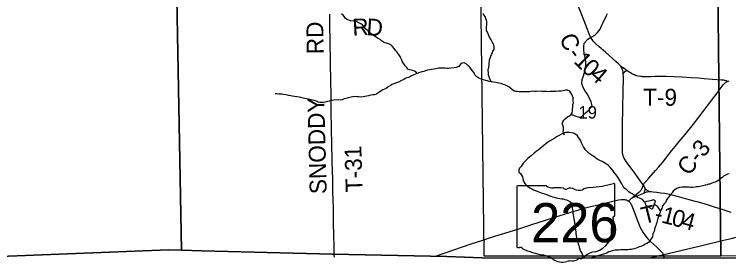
# Model space of a CAD drawing. Extents: x 1985906 to 2360102, y 891258 to 1222054.
# Drawn here: x 2069216 to 2081902, y 971985 to 976398 of the extents above; entities that cross this region are included whole.
import ezdxf

# ---------------------------------------------------------------- set-up
doc = ezdxf.new("R2010")
doc.units = 0
for name, color, linetype in [('GM_X_Adjacent_County', 7, 'Continuous'), ('GM_X_County', 7, 'Continuous'), ('GM_X_County_Road', 7, 'Continuous'), ('GM_X_County_Road_Text', 7, 'Continuous'), ('GM_X_Minor_Lake', 7, 'Continuous'), ('GM_X_Minor_River', 7, 'Continuous'), ('GM_X_Rail_Line', 7, 'Continuous'), ('GM_X_Section', 7, 'Continuous'), ('GM_X_Section_Text', 7, 'Continuous'), ('GM_X_State_Location', 7, 'Continuous'), ('GM_X_State_Route', 7, 'Continuous'), ('GM_X_State_Shield', 7, 'Continuous'), ('GM_X_Township', 7, 'Continuous'), ('GM_X_Township_Road', 7, 'Continuous'), ('GM_X_Township_Road_Text', 7, 'Continuous')]:
    doc.layers.add(name, color=color, linetype=linetype)

msp = doc.modelspace()

# ---------------------------------------------------------------- linework, layer by layer
at = {"layer": 'GM_X_Adjacent_County'}
for points in [[(2071861, 1011952), (2071887, 1008769), (2071889, 1006520), (2071959, 1001676), (2072021, 996047), (2072065, 993379), (2071978, 993380), (2071988, 991894), (2071996, 990692), (2072013, 988008), (2072047, 982707), (2072077, 978079), (2072089, 977430), (2072091, 977317), (2072186, 972205), (2071957, 972211), (2068961, 972095)], [(2068961, 972095), (2071957, 972211), (2072186, 972205), (2072548, 972195), (2074867, 972135), (2076899, 972093), (2077526, 972072), (2080743, 972068), (2082040, 972070), (2083320, 972078), (2085836, 972133), (2087953, 972142), (2092530, 972203), (2095843, 972202)]]:
    msp.add_lwpolyline(points, dxfattribs=at)
at = {"layer": 'GM_X_County'}
msp.add_lwpolyline([(2095843, 972202), (2092530, 972203), (2087953, 972142), (2085836, 972133), (2083320, 972078), (2082040, 972070), (2080743, 972068), (2077526, 972072), (2076899, 972093), (2074867, 972135), (2072548, 972195), (2072186, 972205), (2072091, 977317), (2072089, 977430), (2072077, 978079), (2072047, 982707), (2072013, 988008)], dxfattribs=at)
at = {"layer": 'GM_X_County_Road'}
for points in [[(2079976, 975485), (2079945, 975515), (2079898, 975559), (2079715, 975722), (2079604, 975819), (2079543, 975874), (2079520, 975898), (2079498, 975922), (2079477, 975948), (2079459, 975976), (2079444, 976005), (2079424, 976051), (2079382, 976158), (2079336, 976281), (2079280, 976418), (2079139, 976768), (2079078, 976921)], [(2080031, 975335), (2080031, 975345), (2080026, 975375), (2080020, 975399), (2080012, 975421), (2079996, 975451), (2079988, 975464), (2079976, 975485)], [(2080386, 973366), (2080297, 973492), (2080239, 973572), (2080187, 973643), (2080111, 973742), (2080082, 973783), (2080064, 973810), (2080048, 973839), (2080034, 973867), (2080027, 973887), (2080022, 973910), (2080018, 973934), (2080015, 973968), (2080015, 974066), (2080016, 974182), (2080017, 974265), (2080016, 974322), (2080019, 974507), (2080020, 974652), (2080024, 974803), (2080029, 974967), (2080031, 975065), (2080035, 975230), (2080034, 975295), (2080031, 975335)], [(2080386, 973366), (2080395, 973383), (2080403, 973395), (2080413, 973408), (2080428, 973426), (2080482, 973487), (2080602, 973622), (2080655, 973684), (2080730, 973772), (2080792, 973848), (2080829, 973896), (2080895, 973977), (2080954, 974048), (2081024, 974136), (2081132, 974265), (2081276, 974447), (2081388, 974594), (2081467, 974696), (2081540, 974790), (2081583, 974847), (2081634, 974914), (2081677, 974971), (2081720, 975030), (2081753, 975073), (2081770, 975097), (2081787, 975120), (2081812, 975151), (2081829, 975169), (2081841, 975180), (2081853, 975188), (2081861, 975195), (2081872, 975201), (2081883, 975206)], [(2081883, 975206), (2081895, 975210), (2081909, 975214)], [(2080194, 973146), (2080213, 973162), (2080236, 973181), (2080269, 973207), (2080307, 973237), (2080323, 973249), (2080333, 973258), (2080342, 973267), (2080350, 973278), (2080359, 973290), (2080368, 973311), (2080375, 973331), (2080386, 973366)], [(2080125, 973079), (2080147, 973101), (2080177, 973131), (2080192, 973144), (2080194, 973146)]]:
    msp.add_lwpolyline(points, dxfattribs=at)
at = {"layer": 'GM_X_Minor_Lake'}
for points in [[(2080604, 973077), (2080566, 973099), (2080532, 973089), (2080486, 973077), (2080442, 973074), (2080414, 973058), (2080426, 973016), (2080531, 972942), (2080553, 972949)], [(2080553, 972949), (2080604, 973077)]]:
    msp.add_lwpolyline(points, dxfattribs=at)
at = {"layer": 'GM_X_Minor_River'}
for points in [[(2076368, 975344), (2076350, 975368), (2076322, 975389), (2076291, 975401), (2076263, 975407), (2076233, 975413), (2076207, 975423), (2076184, 975451), (2076158, 975481), (2076136, 975515), (2076110, 975553), (2076095, 975581), (2076079, 975620), (2076067, 975650), (2076045, 975686), (2076011, 975728), (2075988, 975756), (2075962, 975788), (2075934, 975824), (2075905, 975855), (2075879, 975869), (2075825, 975885), (2075797, 975893), (2075770, 975901), (2075738, 975925), (2075712, 975949), (2075680, 975969), (2075633, 975995), (2075607, 976015), (2075577, 976033), (2075550, 976054), (2075524, 976082), (2075496, 976106), (2075455, 976142), (2075429, 976174), (2075399, 976210), (2075371, 976226), (2075344, 976238), (2075300, 976264), (2075270, 976275), (2075238, 976277), (2075185, 976281), (2075155, 976293), (2075127, 976307), (2075100, 976325), (2075080, 976351), (2075054, 976383), (2075026, 976405)], [(2077702, 975195), (2077684, 975197), (2077660, 975251), (2077650, 975284), (2077638, 975318), (2077635, 975352), (2077631, 975404), (2077641, 975458), (2077647, 975490), (2077649, 975528), (2077653, 975563), (2077655, 975589), (2077665, 975619), (2077681, 975655), (2077693, 975681), (2077705, 975713), (2077715, 975741), (2077735, 975775), (2077739, 975815), (2077729, 975852), (2077719, 975878), (2077703, 975908), (2077682, 975946), (2077654, 975994), (2077644, 976020), (2077628, 976048), (2077618, 976077), (2077603, 976111), (2077599, 976147), (2077599, 976173), (2077605, 976213), (2077609, 976245), (2077605, 976271), (2077591, 976322), (2077581, 976348), (2077561, 976380), (2077542, 976414)], [(2079106, 974622), (2079168, 974593), (2079244, 974573), (2079296, 974582), (2079358, 974650), (2079426, 974700), (2079478, 974770), (2079459, 974845), (2079419, 974931), (2079389, 974985), (2079349, 975045), (2079316, 975097), (2079294, 975167), (2079302, 975237), (2079320, 975287), (2079339, 975363), (2079355, 975427), (2079365, 975479), (2079365, 975560), (2079356, 975632), (2079338, 975708), (2079328, 975766), (2079328, 975826), (2079337, 975882), (2079401, 975954), (2079469, 975995), (2079523, 976029), (2079575, 976075), (2079620, 976136), (2079652, 976202), (2079672, 976254), (2079724, 976362), (2079751, 976413)], [(2078971, 974286), (2078978, 974259), (2078964, 974301), (2078966, 974357), (2078968, 974391), (2078955, 974426), (2078947, 974454), (2078955, 974486), (2078973, 974516), (2079003, 974548), (2079042, 974574), (2079074, 974594), (2079102, 974616), (2079120, 974646), (2079126, 974682), (2079128, 974715), (2079132, 974755), (2079136, 974793), (2079144, 974827), (2079142, 974859), (2079142, 974887), (2079138, 974915), (2079130, 974941), (2079115, 974974), (2079101, 975002), (2079079, 975032), (2079039, 975052), (2079010, 975048), (2078960, 975038), (2078920, 975034), (2078885, 975032), (2078831, 975028), (2078783, 975024), (2078728, 975024), (2078700, 975022), (2078672, 975024), (2078626, 975026), (2078583, 975028), (2078555, 975030), (2078489, 975028), (2078454, 975028), (2078426, 975030), (2078362, 975022), (2078335, 975020), (2078295, 975020), (2078257, 975022), (2078217, 975020), (2078182, 975022), (2078154, 975024), (2078124, 975024), (2078096, 975034), (2078069, 975048), (2078037, 975072), (2077997, 975107), (2077964, 975127), (2077924, 975143), (2077888, 975155), (2077860, 975167), (2077821, 975173), (2077793, 975179), (2077765, 975185), (2077680, 975199), (2077650, 975203), (2077622, 975213), (2077591, 975223), (2077549, 975233), (2077523, 975243), (2077493, 975249), (2077466, 975264), (2077428, 975286), (2077396, 975322), (2077384, 975356), (2077351, 975394), (2077329, 975424), (2077299, 975464), (2077272, 975490), (2077240, 975515), (2077204, 975537), (2077172, 975531), (2077141, 975509), (2077109, 975472), (2077065, 975450), (2077025, 975444), (2076968, 975438), (2076926, 975436), (2076900, 975436), (2076868, 975439), (2076839, 975443), (2076795, 975443), (2076751, 975441), (2076702, 975431), (2076668, 975425), (2076630, 975419), (2076596, 975409), (2076553, 975403), (2076517, 975393), (2076487, 975384), (2076453, 975374), (2076418, 975362), (2076370, 975344), (2076338, 975334)], [(2076338, 975334), (2076310, 975324), (2076259, 975298), (2076223, 975276), (2076169, 975262), (2076131, 975240), (2076094, 975220), (2076038, 975192), (2076002, 975180), (2075955, 975164), (2075927, 975152), (2075897, 975134), (2075855, 975110), (2075819, 975080), (2075758, 975058), (2075726, 975034), (2075680, 975003), (2075646, 974979), (2075607, 974969), (2075581, 974965), (2075549, 974959), (2075505, 974947), (2075476, 974943), (2075442, 974935), (2075412, 974933), (2075376, 974927), (2075329, 974929), (2075303, 974933), (2075255, 974935), (2075227, 974931), (2075198, 974925), (2075172, 974921), (2075142, 974915), (2075106, 974903), (2075076, 974893), (2075039, 974877), (2075005, 974873), (2074967, 974881), (2074888, 974875), (2074846, 974865), (2074812, 974855), (2074777, 974847), (2074739, 974837), (2074699, 974833), (2074671, 974829), (2074644, 974829), (2074618, 974839), (2074582, 974855), (2074511, 974874), (2074443, 974888), (2074378, 974902), (2074348, 974908), (2074302, 974918), (2074273, 974924), (2074233, 974934), (2074153, 974942), (2074126, 974948), (2074088, 974956), (2074044, 974966), (2073995, 974972), (2073969, 974976), (2073937, 974980), (2073907, 974980), (2073876, 974982), (2073850, 974982)], [(2080414, 973058), (2080372, 973106), (2080348, 973121), (2080321, 973134), (2080290, 973146), (2080242, 973174), (2080191, 973206), (2080155, 973228), (2080129, 973244), (2080091, 973277), (2080056, 973305), (2080026, 973339), (2080004, 973385), (2079971, 973445), (2079935, 973505), (2079903, 973544), (2079870, 973590), (2079850, 973616), (2079828, 973644), (2079783, 973692), (2079759, 973720), (2079656, 973781), (2079614, 973803), (2079567, 973825), (2079535, 973845), (2079505, 973873), (2079462, 973899), (2079426, 973923), (2079394, 973953), (2079357, 973990), (2079323, 974042), (2079307, 974076), (2079291, 974114), (2079278, 974148), (2079258, 974180), (2079238, 974211), (2079220, 974237), (2079179, 974271), (2079147, 974287), (2079067, 974299), (2079034, 974297), (2079006, 974295), (2078958, 974283), (2078920, 974265), (2078881, 974241), (2078847, 974221), (2078817, 974199), (2078773, 974175), (2078720, 974141), (2078686, 974118), (2078660, 974100), (2078618, 974066), (2078586, 974038), (2078555, 974014), (2078521, 973984), (2078485, 973958), (2078449, 973928), (2078397, 973886), (2078370, 973866), (2078338, 973836), (2078304, 973806), (2078278, 973779), (2078252, 973751), (2078232, 973721), (2078214, 973695), (2078190, 973663), (2078173, 973635), (2078176, 973595), (2078204, 973567), (2078222, 973539), (2078238, 973508), (2078246, 973478), (2078254, 973450), (2078267, 973420), (2078283, 973392), (2078299, 973366), (2078337, 973336), (2078372, 973316), (2078404, 973300), (2078436, 973281), (2078481, 973259), (2078515, 973249), (2078541, 973239), (2078573, 973229), (2078632, 973207), (2078666, 973195), (2078745, 973169), (2078775, 973157), (2078803, 973147), (2078836, 973137)], [(2081913, 973561), (2081883, 973557), (2081843, 973541), (2081809, 973523), (2081783, 973492), (2081750, 973472), (2081726, 973452), (2081696, 973434), (2081660, 973414), (2081634, 973408), (2081593, 973392), (2081567, 973382), (2081543, 973378), (2081517, 973370), (2081487, 973360), (2081442, 973350), (2081416, 973344), (2081392, 973338), (2081360, 973334), (2081332, 973330), (2081307, 973326), (2081257, 973320), (2081231, 973320), (2081195, 973324), (2081164, 973328), (2081106, 973328), (2081068, 973324), (2081029, 973318), (2080981, 973306), (2080953, 973286), (2080919, 973256), (2080899, 973224), (2080869, 973196), (2080842, 973158), (2080810, 973122), (2080790, 973091), (2080786, 973063), (2080748, 973027), (2080734, 973001), (2080720, 972971), (2080716, 972947), (2080698, 972917), (2080688, 972889), (2080680, 972863), (2080664, 972822), (2080658, 972798), (2080644, 972774), (2080630, 972724), (2080626, 972698), (2080612, 972670), (2080606, 972644), (2080596, 972616), (2080586, 972586), (2080582, 972558), (2080568, 972523), (2080556, 972491), (2080548, 972443), (2080522, 972405), (2080506, 972377), (2080478, 972347), (2080447, 972325), (2080421, 972317), (2080393, 972299), (2080341, 972275), (2080315, 972265), (2080290, 972253), (2080262, 972244), (2080228, 972234), (2080194, 972226), (2080170, 972222), (2080141, 972218), (2080109, 972216)], [(2078836, 973137), (2078868, 973129), (2078906, 973125), (2078936, 973121), (2078963, 973117), (2078993, 973108), (2079019, 973104), (2079047, 973092), (2079084, 973074), (2079108, 973048), (2079116, 973018), (2079122, 972984), (2079124, 972956), (2079128, 972926), (2079132, 972900), (2079136, 972867), (2079143, 972835), (2079147, 972801), (2079155, 972763), (2079159, 972733), (2079163, 972705), (2079169, 972651), (2079173, 972606), (2079186, 972536), (2079190, 972502), (2079194, 972462), (2079202, 972430), (2079210, 972402), (2079216, 972376), (2079226, 972345), (2079236, 972305), (2079245, 972279), (2079247, 972253), (2079261, 972225), (2079271, 972189), (2079297, 972157), (2079309, 972123), (2079308, 972072)], [(2080694, 972906), (2080682, 972922), (2080660, 972952), (2080640, 972982), (2080603, 973010), (2080582, 973021)], [(2080109, 972216), (2080085, 972212), (2080059, 972212), (2080033, 972214), (2080008, 972215), (2079982, 972213), (2079952, 972209), (2079928, 972209), (2079884, 972205), (2079859, 972203), (2079833, 972197), (2079801, 972185), (2079775, 972176), (2079747, 972160), (2079718, 972150), (2079658, 972130), (2079465, 972071)]]:
    msp.add_lwpolyline(points, dxfattribs=at)
at = {"layer": 'GM_X_Rail_Line'}
msp.add_lwpolyline([(2080494, 972069), (2080828, 972148), (2081401, 972286), (2081786, 972379), (2081947, 972418), (2082172, 972472), (2082349, 972515), (2082494, 972547), (2082628, 972572), (2082747, 972593), (2082836, 972607), (2082921, 972619), (2083045, 972632), (2083617, 972692), (2084439, 972777), (2085170, 972852), (2086125, 972950), (2086596, 973001)], dxfattribs=at)
at = {"layer": 'GM_X_Section'}
for points in [[(2081702, 977387), (2086530, 977506), (2087165, 977509), (2087211, 972176), (2081764, 972104)], [(2077497, 977310), (2081702, 977387), (2081764, 972104), (2077558, 972100), (2077557, 972150)]]:
    msp.add_lwpolyline(points, close=True, dxfattribs=at)
at = {"layer": 'GM_X_State_Route'}
msp.add_lwpolyline([(2076714, 972108), (2076833, 972149), (2077019, 972213), (2077331, 972318), (2077518, 972380), (2077674, 972431), (2078003, 972535), (2078191, 972595), (2078425, 972671), (2078629, 972737), (2078833, 972800), (2078989, 972850), (2079115, 972889), (2079241, 972926), (2079400, 972969), (2079607, 973020), (2079847, 973078), (2079944, 973099), (2079993, 973107), (2080026, 973109), (2080043, 973108), (2080060, 973107), (2080072, 973104), (2080086, 973099), (2080099, 973093), (2080114, 973086), (2080122, 973081), (2080125, 973079), (2080132, 973073), (2080140, 973066), (2080151, 973053), (2080161, 973039), (2080169, 973025), (2080183, 972995), (2080208, 972934), (2080287, 972718), (2080311, 972658), (2080332, 972613), (2080354, 972570), (2080379, 972527), (2080405, 972487), (2080435, 972447), (2080466, 972410), (2080500, 972375), (2080633, 972253), (2080680, 972208), (2080703, 972184), (2080714, 972171), (2080724, 972158), (2080730, 972148), (2080735, 972140), (2080739, 972130), (2080744, 972111), (2080750, 972089), (2080752, 972074)], dxfattribs=at)
at = {"layer": 'GM_X_State_Shield'}
for p, q in [((2078138, 973331), (2078138, 972274)), ((2078665, 973349), (2078155, 973349)), ((2079878, 972822), (2079878, 973375)), ((2079878, 972822), (2079878, 972822))]:
    msp.add_line(p, q, dxfattribs=at)
for centre, major_axis, start_param, end_param in [((2078158, 973333), (20.2, 0), 1.712693, 3.28349), ((2078786, 973471), (196, 0), 4.042523, 4.731795), ((2078851, 972756), (702, 0), 1.404758, 1.657858), ((2079093, 973216), (117, 0), 0.950623, 2.079405), ((2079494, 973026), (371, 0), 1.699011, 2.107814), ((2079258, 974789), (1845, 0), 4.814394, 5.042369), ((2079859, 973377), (19.4, 0), 6.141152, 7.989035), ((2079010, 973338), (56.4, 0), 3.836095, 5.185415), ((2079244, 973384), (141, 0), 4.081561, 5.145723), ((2079857, 972820), (20.7, 0), 5.05454, 6.418171), ((2079874, 972782), (30, 0), 1.883978, 3.671073), ((2079683, 972712), (180, 0), 5.934695, 6.695948), ((2079362, 972521), (462, 0), 5.101752, 6.440018), ((2079947, 972591), (131, 0), 2.387724, 3.262537), ((2078158, 972272), (20.3, 0), 3.00124, 4.508301), ((2078161, 972380), (155, 0), 4.665946, 4.897461), ((2078193, 972213), (56, 0), 0.519207, 1.627899), ((2078899, 973162), (1333, 0), 4.195997, 4.488961), ((2079556, 971977), (253, 0), 1.647645, 2.488434), ((2078502, 971799), (417, 0), 0.823519, 1.323587), ((2079125, 972129), (141, 0), 4.691044, 5.507374), ((2079253, 972026), (39.7, 0), 1.147584, 2.315152), ((2079236, 972172), (149, 0), 4.937069, 5.64225), ((2078953, 972208), (265, 0), 4.026481, 4.996735), ((2079106, 971842), (217, 0), 1.495662, 1.94098)]:
    msp.add_ellipse(centre, major_axis=major_axis, ratio=0.8, start_param=start_param, end_param=end_param, dxfattribs=at)
at = {"layer": 'GM_X_Township'}
msp.add_lwpolyline([(2095843, 972202), (2092530, 972203), (2087953, 972142), (2085836, 972133), (2083320, 972078), (2082040, 972070), (2080743, 972068), (2077526, 972072), (2076899, 972093), (2074867, 972135), (2072548, 972195), (2072186, 972205), (2072091, 977317), (2072089, 977430), (2072077, 978079), (2072047, 982707), (2072013, 988008)], dxfattribs=at)
at = {"layer": 'GM_X_Township_Road'}
for points in [[(2074900, 972082), (2074898, 972116), (2074897, 972182), (2074894, 972296), (2074891, 972460), (2074886, 972706), (2074885, 972820), (2074883, 972967), (2074881, 973082), (2074875, 973262), (2074870, 973491), (2074868, 973591), (2074862, 973802), (2074859, 973896), (2074856, 974006), (2074853, 974096), (2074850, 974345), (2074847, 974472), (2074845, 974579), (2074844, 974709), (2074842, 974822), (2074841, 974934), (2074840, 975035), (2074838, 975144), (2074837, 975210), (2074835, 975291), (2074833, 975456), (2074831, 975628), (2074828, 975838), (2074826, 975987), (2074822, 976142), (2074820, 976329), (2074820, 976387), (2074821, 976402)], [(2079976, 975485), (2079989, 975477), (2079999, 975471), (2080043, 975440), (2080045, 975439)], [(2080031, 975335), (2080042, 975355), (2080046, 975362), (2080050, 975369), (2080054, 975375), (2080060, 975381), (2080065, 975386), (2080072, 975390), (2080077, 975393), (2080084, 975395), (2080101, 975401)], [(2080045, 975439), (2080101, 975401)], [(2080101, 975401), (2080146, 975370), (2080177, 975350), (2080191, 975341), (2080207, 975334), (2080227, 975326), (2080247, 975318), (2080265, 975313), (2080295, 975305), (2080341, 975298), (2080356, 975296), (2080366, 975295), (2080381, 975295), (2080450, 975295), (2080519, 975295), (2080588, 975296), (2080702, 975296), (2080791, 975297), (2080928, 975293), (2081076, 975286), (2081236, 975275), (2081367, 975266), (2081465, 975259), (2081612, 975248), (2081776, 975235), (2081808, 975231), (2081830, 975228), (2081845, 975224), (2081860, 975219), (2081875, 975212), (2081883, 975206)], [(2080386, 973366), (2080407, 973326), (2080414, 973312), (2080420, 973302)], [(2080194, 973146), (2080210, 973151), (2080248, 973163), (2080309, 973187), (2080393, 973222)], [(2080393, 973222), (2080401, 973235), (2080405, 973242), (2080409, 973250), (2080411, 973257), (2080414, 973265), (2080416, 973275), (2080418, 973283), (2080419, 973292), (2080420, 973302)], [(2080393, 973222), (2080416, 973231), (2080447, 973242), (2080463, 973245), (2080479, 973248), (2080489, 973249), (2080498, 973249)], [(2080420, 973302), (2080423, 973297), (2080435, 973285), (2080449, 973274), (2080464, 973265), (2080479, 973258), (2080498, 973249)], [(2080498, 973249), (2080528, 973249), (2080561, 973246), (2080629, 973239), (2080697, 973229), (2080767, 973219), (2080849, 973204), (2080917, 973187), (2081027, 973156), (2081154, 973121), (2081281, 973087), (2081359, 973065), (2081517, 973018), (2081642, 972979), (2081721, 972956), (2081783, 972936), (2081939, 972883)]]:
    msp.add_lwpolyline(points, dxfattribs=at)

# ---------------------------------------------------------------- texts
at = {"layer": 'GM_X_County_Road_Text'}
for s, rotation, p in [('C', 292.3573, (2078891, 975985)), ('-', 306.7738, (2079026, 975686)), ('1', 316.2716, (2079135, 975547)), ('0', 318.0623, (2079276, 975412)), ('4', 318.9742, (2079418, 975285)), ('C-3', 51.1271, (2081193, 973514))]:
    msp.add_text(s, height=300, rotation=rotation, dxfattribs=at).set_placement(p)
at = {"layer": 'GM_X_Section_Text'}
msp.add_text('19', height=221, rotation=0, dxfattribs=at).set_placement((2079234, 974546))
at = {"layer": 'GM_X_State_Location'}
for s in ['s', 'r']:
    msp.add_text(s, height=1, dxfattribs=at).set_placement((2078988, 972732))
msp.add_text('226', height=1, rotation=0, dxfattribs=at).set_placement((2078635, 972659))
at = {"layer": 'GM_X_State_Shield'}
msp.add_text('226', height=696.1, dxfattribs=at).set_placement((2078393, 972348))
at = {"layer": 'GM_X_Township_Road_Text'}
for s, rotation, p in [('RD', 90.993, (2074711, 975691)), ('R', 2.7507, (2075226, 976015)), ('D', 355.9166, (2075463, 976027)), ('T-9', 359.5431, (2080382, 974777)), ('SNODDY', 91.4671, (2074764, 973207)), ('T-31', 91.7854, (2075403, 973242)), ('T', 13.8684, (2080390, 972668)), ('1', 345.818, (2080691, 972702)), ('0', 344.8145, (2080869, 972657)), ('-', 350.8713, (2080576, 972720)), ('4', 344.6636, (2081047, 972609))]:
    msp.add_text(s, height=300, rotation=rotation, dxfattribs=at).set_placement(p)

doc.saveas('drawing.dxf')
